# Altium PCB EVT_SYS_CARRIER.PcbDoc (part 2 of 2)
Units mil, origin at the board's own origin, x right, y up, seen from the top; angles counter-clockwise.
Board outline 3937.01 x 3149.61 mil, 4 copper layers (Top Layer, Mid-Layer 1, Mid-Layer 2, Bottom Layer), stack 63.036 mil thick; 92 components, 67 nets, 529 pads, 132 vias.
Unrouted connection lines stored in the file: 166.
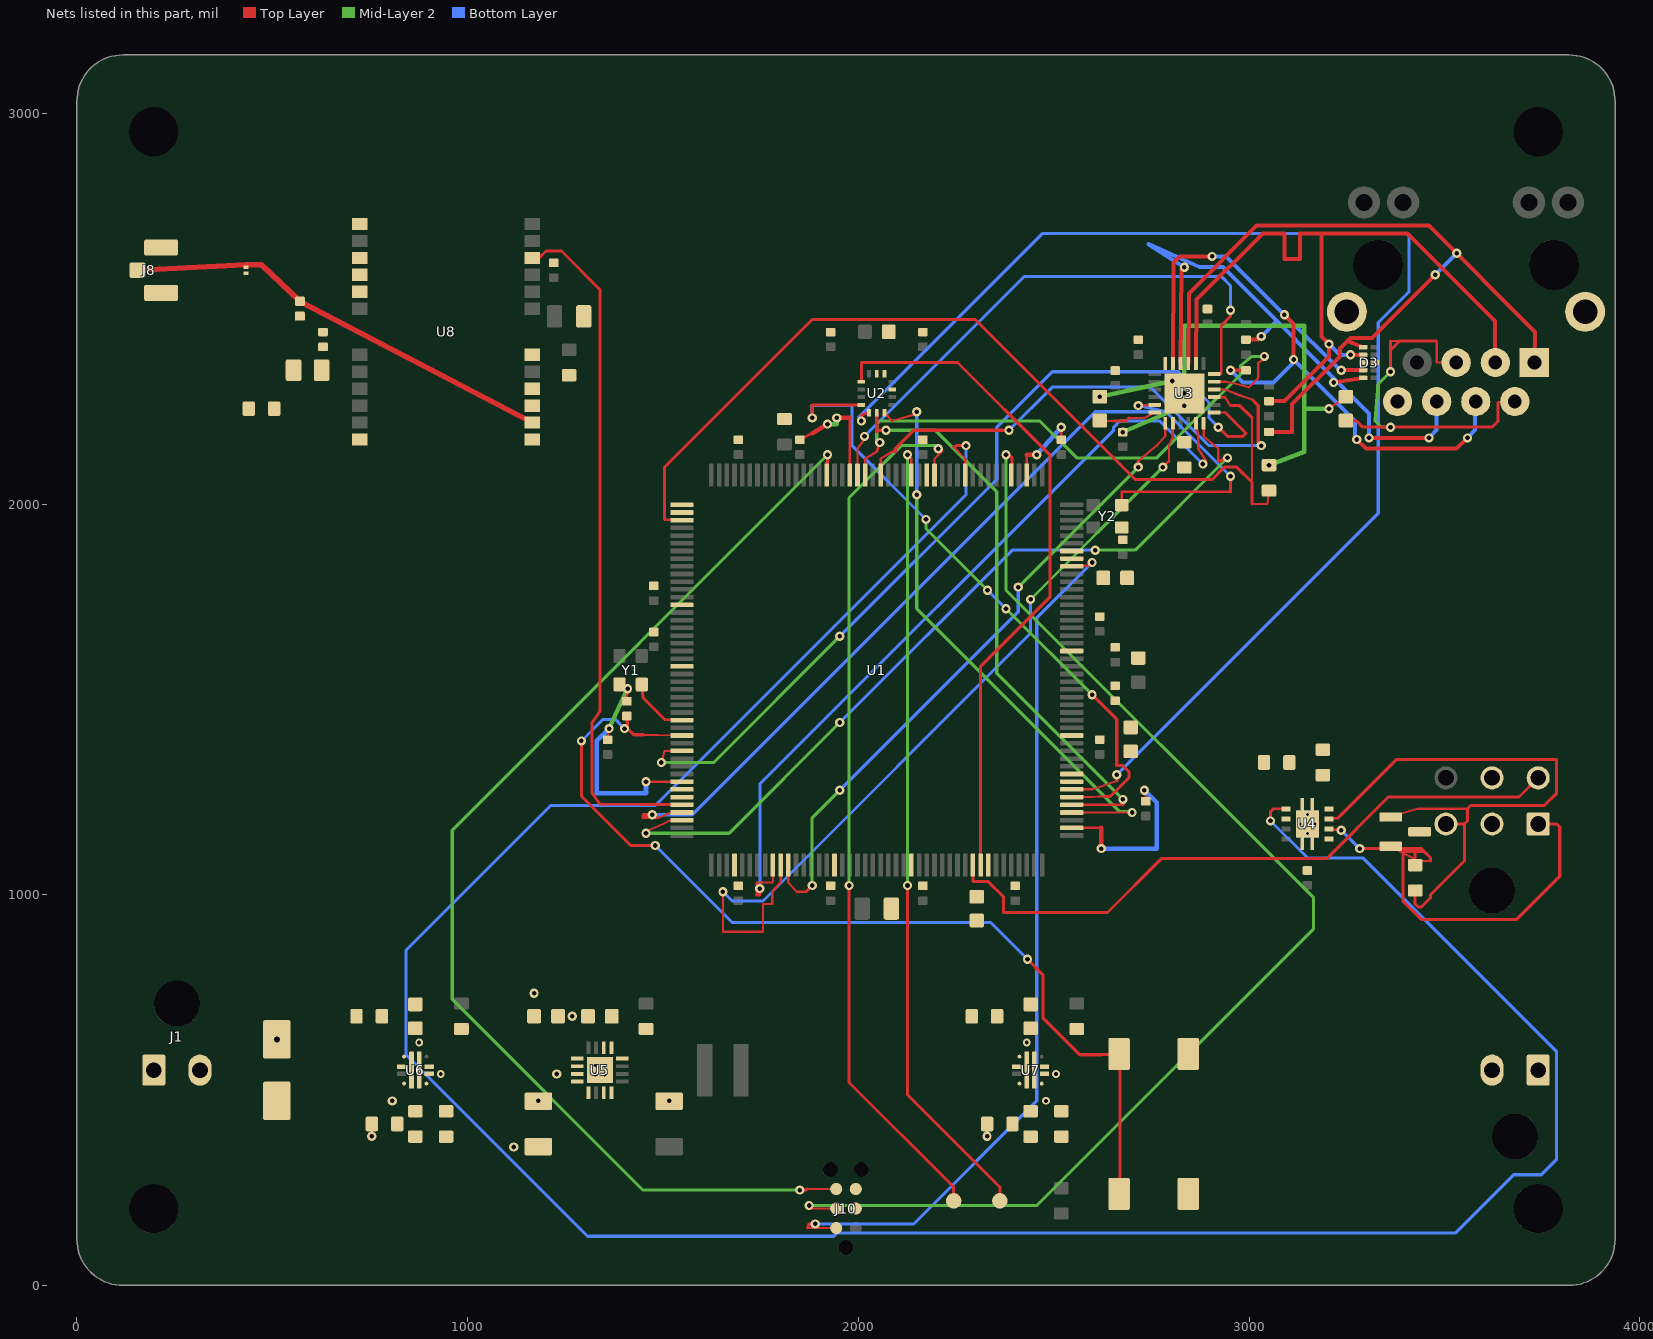
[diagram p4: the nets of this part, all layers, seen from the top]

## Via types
v1: diameter 23.62, hole 11.81, Top Layer to Bottom Layer, 121 vias
v2: diameter 19.68, hole 9.84, Top Layer to Bottom Layer, 5 vias
v3: diameter 15.75, hole 7.87, Top Layer to Bottom Layer, 4 vias
v4: diameter 31.5, hole 15.75, Top Layer to Bottom Layer, 2 vias

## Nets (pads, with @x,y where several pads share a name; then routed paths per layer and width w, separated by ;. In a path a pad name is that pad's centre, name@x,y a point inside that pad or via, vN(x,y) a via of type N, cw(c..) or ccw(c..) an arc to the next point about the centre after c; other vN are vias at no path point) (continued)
CAN_TX: U1.143 U4.1 | length 6963.6
  Top Layer w5.91: 2244.09,2145.67 2273.62,2116.14 U1.143@2273.62,2073.82
  Top Layer w7.87: 2244.09,2145.67 2251.97,2149.61 v1(2275.59,2149.61) ; v1(3055.12,1188.98) 3055.12,1212.6 3062.99,1220.47 U4.1@3094.49,1219.49
  Bottom Layer w7.87: v1(2275.59,2149.61) 2275.59,2023.62 1480.32,1228.35 1212.6,1228.35 842.52,858.27 842.52,590.55 1307.09,125.98 1937.01,125.98 1944.88,133.86 3527.56,133.86 3677.17,283.46 3748.03,283.46 3787.4,322.83 3787.4,598.43 3291.34,1094.49 3149.61,1094.49 v1(3055.12,1188.98)
DEBUG_RX: TP2.1 U1.150 | length 2063.5
  Top Layer w5.91: v1(2125.98,2125.98) 2135.83,2116.14 U1.150@2135.83,2073.82
  Top Layer w7.87: v1(2125.98,1023.62) 2125.98,488.19 2362.2,251.97 TP2.1@2362.2,216.54
  Mid-Layer 2 w7.87: v1(2125.98,1023.62) v1(2125.98,2125.98)
DEBUG_TX: TP1.1 U1.147 | length 2278.8
  Top Layer w5.91: U1.147@2194.88,2073.82 2194.88,2116.14 v1@2214.57,2135.83
  Top Layer w7.87: v1(1976.38,1023.62) 1976.38,519.68 2244.09,251.97 TP1.1@2244.09,216.54 ; v1(2204.72,2141.73) v1@2214.57,2135.83
  Mid-Layer 2 w7.87: v1(1976.38,1023.62) 1976.38,2015.75 2110.24,2149.61 2196.85,2149.61 v1(2204.72,2141.73)
ETH_50M: U1.41 U3.5 Y2.3 | length 2576.5
  Top Layer w5.91: 1448.82,1196.85 1488.19,1196.85 1519.68,1210.63 U1.41@1548.23,1210.63 ; Y2.3@2674.21,1997.05 2674.41,2031.5 2952.76,2031.5
  Top Layer w7.87: 1448.82,1196.85 1448.82,1204.72 v1(1472.44,1204.72) ; v1(2716.54,2251.97) 2724.41,2251.97 U3.5@2758.37,2253.94 ; 2952.76,2031.5 v1(2952.76,2070.87)
  Bottom Layer w7.87: v1(1472.44,1204.72) 1574.8,1204.72 2606.3,2236.22 2787.4,2236.22 ; v1(2716.54,2251.97) 2787.4,2236.22 ; v1(2952.76,2070.87) 2787.4,2236.22
ETH_CRS_DV: U1.53 U3.11 | length 2091.7
  Top Layer w5.91: 1740.16,1000 1740.16,1031.5 1781.5,1031.5 U1.53@1781.5,1075.79 ; U3.11@2864.17,2207.19 2870.08,2173.23 2870.08,2141.73 v1@2889.76,2110.24
  Top Layer w7.87: 1740.16,1000 1748.03,1000 v1(1748.03,1015.75) ; v1(2881.89,2102.36) v1@2889.76,2110.24
  Bottom Layer w7.87: v1(1748.03,1015.75) 1748.03,1283.46 2653.54,2188.98 2653.54,2196.85 2669.29,2212.6 2771.65,2212.6 v1(2881.89,2102.36)
ETH_CT: C63.1 pad.2@3680.32,2262.2 pad.5@3530.32,2362.2 | length 1348.1
  Top Layer w5.91: 3362.2,2417.32 3480.32,2417.32 3480.32,2362.2 pad.5@3530.32,2362.2
  Top Layer w7.87: C63.1@3248.03,2213.58 3275.59,2212.6 3291.34,2196.85 v1(3362.2,2196.85) 3622.05,2196.85 3637.8,2212.6 3637.8,2259.84 pad.2@3680.32,2262.2 ; 3362.2,2417.32 v1(3362.2,2338.58) 3362.2,2393.7 3385.83,2417.32 3480.32,2417.32
  Mid-Layer 2 w7.87: 3322.83,2212.6 3330.71,2307.09 ; 3322.83,2212.6 3338.58,2196.85 ; 3322.83,2212.6 3338.58,2196.85 ; 3322.83,2212.6 3330.71,2307.09 ; 3330.71,2307.09 v1(3362.2,2338.58) 3330.71,2307.09 ; 3338.58,2196.85 v1(3362.2,2196.85) 3338.58,2196.85
ETH_MDC: U1.33 U3.13 | length 2261.6
  Top Layer w5.91: v1(1496.06,1338.58) 1503.94,1368.11 U1.33@1548.23,1368.11 ; U3.13@2910.93,2234.25 2938.98,2234.25
  Top Layer w7.87: v1(2921.26,2196.85) 2944.88,2173.23 2984.25,2173.23 2992.13,2181.1 2938.98,2234.25
  Mid-Layer 2 w7.87: v1(1496.06,1338.58) 1629.92,1338.58 v1(1952.76,1661.42)
  Bottom Layer w7.87: v1(1952.76,1661.42) 2354.33,2062.99 2354.33,2196.85 2496.06,2338.58 2818.9,2338.58 2897.64,2259.84 2897.64,2220.47 v1(2921.26,2196.85)
ETH_MDIO: U1.42 U3.12 | length 2127.8
  Top Layer w5.91: v1(1456.69,1157.48) 1464.57,1165.35 1500,1181.1 1519.68,1190.94 U1.42@1548.23,1190.94 ; U3.12@2883.86,2207.19 2883.86,2173.23 2921.26,2141.73 2921.26,2110.24
  Top Layer w7.87: 2921.26,2110.24 2929.13,2110.24 2937.01,2118.11 v1(2944.88,2118.11)
  Mid-Layer 2 w7.87: v1(1456.69,1157.48) 1669.29,1157.48 v1(1952.76,1440.94) ; v1(2606.3,1881.89) 2708.66,1881.89 v1(2944.88,2118.11)
  Bottom Layer w7.87: v1(1952.76,1440.94) 2393.7,1881.89 v1(2606.3,1881.89)
ETH_NRST: R605.1 U1.3 U3.15 | length 2509.2
  Top Layer w5.91: U3.15@2910.93,2273.62 2938.98,2273.62 2952.76,2251.97 ; 3007.87,2220.47 3007.87,2000 3047.24,2000 R605.1@3051.18,2034.45
  Top Layer w7.87: U1.3@1548.23,1958.66 1503.94,1960.63 1503.94,2094.49 1881.89,2472.44 2299.21,2472.44 2708.66,2062.99 2905.51,2062.99 2937.01,2094.49 2968.5,2094.49 3007.87,2055.12 3007.87,2000 ; 2952.76,2251.97 2976.38,2251.97 3007.87,2220.47
ETH_RXD0: U1.54 U3.8 | length 2174.6
  Top Layer w5.91: v1(1653.54,1007.87) 1653.54,905.51 1755.91,905.51 1755.91,976.38 1779.53,976.38 1779.53,1007.87 1801.18,1031.5 U1.54@1801.18,1075.79 ; 2795.28,2110.24 2795.28,2149.61 2805.12,2173.23 U3.8@2805.12,2207.19
  Top Layer w7.87: v1(2779.53,2094.49) 2795.28,2110.24
  Mid-Layer 2 w7.87: v1(2440.94,1755.91) v1(2779.53,2094.49)
  Bottom Layer w7.87: v1(1653.54,1007.87) 1677.17,984.25 1755.91,984.25 2440.94,1669.29 v1(2440.94,1755.91)
ETH_RXD1: U1.55 U3.7 | length 1682.1
  Top Layer w5.91: U1.55@1820.87,1075.79 1820.87,1031.5 1842.52,1007.87 1866.14,1007.87 ; 2716.54,2110.24 2763.78,2149.61 2785.43,2173.23 U3.7@2785.43,2207.19
  Top Layer w7.87: 1866.14,1007.87 v1(1881.89,1023.62) ; v1(2716.54,2094.49) 2716.54,2110.24
  Mid-Layer 2 w7.87: v1(1881.89,1023.62) 1881.89,1196.85 v1(1952.76,1267.72) ; v1(2409.45,1787.4) v1(2716.54,2094.49)
  Bottom Layer w7.87: v1(1952.76,1267.72) 2409.45,1724.41 v1(2409.45,1787.4)
ETH_RXN: D3.5 pad.6@3480.32,2262.2 R604.1 U3.22 | length 1595.8
  Top Layer w10.24: U3.22@2824.8,2359.74 2826.77,2602.36 2830.71,2606.3 v1(2834.65,2606.3) ; R604.1@2992.13,2420.87 3023.62,2421.26 v1(3031.5,2429.13) ; v1(3216.54,2311.02) D3.5@3291.93,2322.83 ; v1(3307.09,2169.29) v1(3460.63,2169.29)
  Bottom Layer w10.24: v1(2834.65,2606.3) 2742.34,2665.35 2874.02,2606.3 2933.07,2606.3 3307.09,2232.28 v1(3307.09,2169.29) ; v1(3031.5,2429.13) 3070.87,2468.5 ; v1(3216.54,2311.02) 3216.54,2314.96 v1@3220.47,2318.9 ; v1(3460.63,2169.29) 3480.32,2188.98 pad.6@3480.32,2262.2
ETH_RXP: D3.4 pad.4@3580.32,2262.2 R603.1 U3.23 | length 1912.3
  Top Layer w10.24: U3.23@2805.12,2359.74 2807.09,2618.11 2822.83,2633.86 v1(2905.51,2633.86) ; v1(2952.76,2342.52) 2960.63,2342.52 R603.1@2992.13,2342.13 ; v1(3090.55,2484.25) 3114.17,2460.63 v1(3114.17,2370.08) ; v1(3236.22,2342.52) D3.4@3291.93,2342.52 ; v1(3275.59,2165.35) 3299.21,2141.73 3531.5,2141.73 v1(3559.06,2169.29)
  Bottom Layer w10.24: v1(2905.51,2633.86) 2940.94,2633.86 v1(3090.55,2484.25) 3232.28,2342.52 v1(3236.22,2342.52) ; v1(2952.76,2342.52) 2984.25,2311.02 3062.99,2311.02 v1@3118.11,2366.14 ; v1(3114.17,2370.08) 3271.65,2212.6 3271.65,2169.29 v1(3275.59,2165.35) ; v1(3559.06,2169.29) 3578.74,2188.98 pad.4@3580.32,2262.2
ETH_TX_EN: U1.154 U3.16 | length 1386.2
  Top Layer w5.91: U1.154@2057.09,2073.82 2057.09,2116.14 2086.61,2133.86 2094.49,2133.86 ; U3.16@2910.93,2293.31 2938.98,2293.31 2972.44,2279.53 3007.87,2267.72
  Top Layer w7.87: 2094.49,2133.86 2094.49,2141.73 2141.73,2188.98 v1(2385.83,2188.98) ; 3007.87,2267.72 3023.62,2251.97 3023.62,2157.48 v1(3031.5,2149.61)
  Bottom Layer w7.87: v1(2385.83,2188.98) 2496.06,2299.21 2748.03,2299.21 2897.64,2149.61 v1(3031.5,2149.61)
ETH_TXD0: U1.156 U3.17 | length 1495
  Top Layer w5.91: U1.156@2017.72,2073.82 2017.72,2116.14 2047.24,2133.86 v1(2055.12,2157.48) ; U3.17@2910.93,2312.99 2938.98,2312.99 2968.5,2307.09 3000,2299.21 3023.62,2322.83 3023.62,2362.2 v1@3039.37,2370.08
  Top Layer w7.87: v1@3039.37,2370.08 v1(3039.37,2377.95)
  Mid-Layer 2 w7.87: v1(2055.12,2157.48) 2047.24,2165.35 2047.24,2204.72 2055.12,2212.6 2464.57,2212.6 2559.06,2118.11 2763.78,2118.11 2978.35,2330.71 2978.35,2354.33 3007.87,2377.95 v1(3039.37,2377.95)
ETH_TXD1: U1.157 U3.18 | length 1476.1
  Top Layer w5.91: U1.157@1998.03,2073.82 1998.03,2116.14 1998.03,2141.73 2015.75,2165.35 v1(2015.75,2173.23) ; U3.18@2910.93,2332.68 2929.13,2332.68 2929.13,2456.69
  Top Layer w7.87: 2929.13,2456.69 2952.76,2480.32 v1(2952.76,2496.06)
  Bottom Layer w7.87: v1(2015.75,2173.23) 2425.2,2582.68 2929.13,2582.68 2952.76,2559.06 v1(2952.76,2496.06)
ETH_TXN: D3.2 pad.3@3630.32,2362.2 R602.1 U3.20 | length 1951.1
  Top Layer w10.24: U3.20@2864.17,2359.74 2866.14,2523.62 3035.43,2692.91 3090.55,2692.91 3090.55,2627.18 3129.92,2627.18 3129.92,2692.91 3405.51,2692.91 3629.92,2468.5 3629.92,2440.94 pad.3@3630.32,2362.2 ; R602.1@3051.18,2263.39 3090.55,2263.78 3204.72,2377.95 v1(3204.72,2409.45) 3185.04,2429.13 3185.04,2692.91 ; v1(3259.84,2381.89) D3.2@3291.93,2381.89
  Bottom Layer w10.24: v1(3204.72,2409.45) 3232.28,2381.89 v1(3259.84,2381.89)
ETH_TXP: D3.1 pad.1@3730.32,2362.2 R601.1 U3.21 | length 2094
  Top Layer w10.24: U3.21@2844.49,2359.74 2846.46,2539.37 3019.68,2712.6 3460.63,2712.6 3732.28,2440.94 pad.1@3730.32,2362.2 ; R601.1@3051.18,2184.65 3110.24,2185.04 3110.24,2255.91 3232.28,2377.95 3232.28,2397.64 3251.97,2417.32 ; D3.1@3291.93,2401.57 3251.97,2417.32 ; v1(3476.38,2586.61) 3314.96,2425.2 3259.84,2425.2 3255.91,2421.26 3251.97,2417.32
  Bottom Layer w10.24: v1(3476.38,2586.61) v1(3531.5,2641.73)
GND: C1.2 C2.2 C3.2 C4.2 C6D.2 C7D.2 C10.2 C11.2 C12.2 C13.2 C14.2 C15.2 C20.2 C21.2 C22.2 C40.2 C60.2 C61.2 C62.2 C63.2 C64.2 C65.2 C80.2 C81.2 C82.2 C100.2 C101.2 C102.2 C103.2 C104.2 C105.2 C106.2 C107.2 C108.2 C109.2 C110.2 C111.2 C112.2 C113.2 C114.2 C115.2 D1.2 D3.3 D3.8 D8.2 J1.2 J8.2 J10.3 J10.5 pad.2@2844.49,234.25 pad.2@2844.49,592.52 pad.2@3622.05,551.18 pad.2@3622.05,1181.1 pad.3@3436.52,1161.42 pad.5@3622.05,1299.21 R1.2 R2.2 R10.2 R41.2 R42.2 R63.2 R73.2 R81.2 R600.2 R605.2 U1.14 U1.22 U1.37 U1.48 U1.61 U1.71 U1.90 U1.102 U1.113 U1.126 U1.135 U1.148 U1.158 U2.6 U2.7 U2.9 U3.25 U4.2 U4.9 U5.5 U5.6 U5.15 U5.16 U5.17 U6.8 U7.8 U8.10 U8.12 U8.13 U8.24 Y1.2 Y2.2 | length 2972.3
  Top Layer w5.91: C115.2@1407.48,1495.28 v1(1409.45,1527.56) ; v1(1456.69,1289.37) U1.37@1548.23,1289.37 ; C113.2@1850.39,2164.57 1881.89,2181.1 ; U1.158@1978.35,2073.82 1978.35,2220.47 ; U1.135@2431.1,2073.82 2431.1,2125.98 ; C111.2@2519.69,2164.57 v1(2519.68,2196.85) ; U1.90@2546.26,1171.26 2622.05,1171.26 ; v1(2732.28,1267.72) C107.2@2736.22,1239.37 ; v1(3204.72,2244.09) C63.2@3248.03,2274.61 ; C102.2@1358.27,1396.85 v1(1362.2,1425.2) C102.2@1358.27,1396.85
  Top Layer w11.81: 1881.89,2181.1 v1(1921.26,2204.72) ; v1(1944.88,2220.47) 1978.35,2220.47 ; 2431.1,2125.98 v1(2456.69,2125.98) ; v1(2622.05,1118.11) 2622.05,1171.26
  Mid-Layer 2 w11.81: v1(1362.2,1425.2) v1(1409.45,1527.56) ; v1(1921.26,2204.72) 1944.88,2204.72 v1(1944.88,2220.47) ; v1(2618.11,2274.61) v1(2803.15,2314.96) ; v1(2677.16,2184.25) v1(2834.65,2251.97) ; v1(2834.65,2283.46) 2834.65,2456.69 3141.73,2456.69 3141.73,2133.86 v1(3051.18,2099.41) ; 3141.73,2244.09 v1(3204.72,2244.09)
  Bottom Layer w11.81: v1(1362.2,1425.2) 1330.71,1393.7 1330.71,1259.84 1456.69,1259.84 v1(1456.69,1289.37) ; v1(2456.69,2125.98) v1(2519.68,2196.85) ; v1(2622.05,1118.11) 2763.78,1118.11 2763.78,1236.22 v1(2732.28,1267.72)
  other v1: 1181.1,472.44 1515.75,472.44 1267.72,688.98
  other v2: 931.1,541.34 2505.91,541.34
  other v3: 1326.77,539.37 1350.39,539.37 1326.77,562.99 1350.39,562.99
  other v4: 511.81,629.92
GNSS_BCKP_LOCAL: R82.1 U8.22
GNSS_BIAS_FILTER: C82.1 L80.1 R80.2
GNSS_PPS: U1.40 U8.3 | length 1761.7
  Top Layer w7.87: U8.3@1165.35,2629.92 1171.26,2627.95 1181.1,2627.95 1200.79,2647.64 1240.16,2647.64 1338.58,2549.21 1338.58,1468.5 1318.9,1440.94 1318.9,1259.84 1338.58,1232.28 U1.40@1548.23,1230.31
GNSS_RF: D8.1 J8.1 L80.2 U8.11 | length 1123.8
  Top Layer w14.17: J8.1@155.51,2598.43 433.07,2612.6 472.44,2612.6 570.87,2518.9 U8.11@1165.35,2208.66
GNSS_RX_EXT: U1.96 U8.21
GNSS_TX_EXT: U1.97 U8.20
GNSS_VCC_RF: R80.1 U8.9
GNSS_VUSB_LOCAL: R81.1 U8.7
IMU_DRDY: U1.80 U2.4 | length 1752.9
  Top Layer w7.87: U2.4@2007.87,2312.99 2007.87,2362.2 2253.94,2362.2 2490.16,2125.98 2490.16,1761.81 2312.99,1584.65 U1.80@2312.99,1075.79
IMU_MISO: U1.94 U2.1 | length 1714.6
  Top Layer w5.91: U1.94@2546.26,1250 2598.43,1250 2629.92,1251.97
  Top Layer w7.87: v1(1881.89,2220.47) 1881.89,2253.94 U2.1@2007.38,2253.94 ; v1(2598.43,1511.81) 2661.42,1448.82 2661.42,1330.71 2677.17,1330.71 2692.91,1314.96 2692.91,1299.21 2645.67,1251.97 2629.92,1251.97
  Mid-Layer 2 w7.87: v1(2173.23,1960.63) 2173.23,1937.01 v1(2330.71,1779.53) ; v1(2377.95,1732.28) v1(2598.43,1511.81)
  Bottom Layer w7.87: v1(1881.89,2220.47) 1881.89,2251.97 1984.25,2251.97 1984.25,2181.1 1984.25,2149.61 v1(2173.23,1960.63) ; v1(2330.71,1779.53) v1(2377.95,1732.28)
IMU_MOSI: U1.95 U2.14 | length 3478
  Top Layer w5.91: U1.95@2546.26,1269.68 2598.43,1269.68 2661.42,1291.34
  Top Layer w7.87: v1(2007.87,2212.6) 2007.87,2228.35 U2.14@2027.56,2233.76 ; 2661.42,1291.34 v1(2661.42,1307.09)
  Bottom Layer w7.87: v1(2007.87,2212.6) 2000,2220.47 2472.44,2692.91 3401.57,2692.91 3409.45,2685.04 3409.45,2543.31 3330.71,2464.57 3330.71,1976.38 v1(2661.42,1307.09)
IMU_NSS: U1.92 U2.12 | length 1522.3
  Top Layer w5.91: U2.12@2066.93,2233.76 2086.61,2212.6 v1@2141.73,2228.35 ; U1.92@2546.26,1210.63 2598.43,1210.63 v1(2700.79,1210.63)
  Top Layer w7.87: v1@2141.73,2228.35 v1(2149.61,2236.22)
  Mid-Layer 2 w7.87: v1(2149.61,2023.62) 2149.61,1732.28 2669.29,1212.6 v1@2700.79,1212.6
  Bottom Layer w7.87: v1(2149.61,2023.62) v1(2149.61,2236.22)
IMU_SCK: U1.93 U2.13 | length 1487.8
  Top Layer w5.91: U1.93@2546.26,1230.31 2598.43,1230.32 2677.17,1230.32
  Top Layer w7.87: U2.13@2047.24,2233.76 2047.24,2185.04 2055.12,2188.98 v1(2070.87,2188.98) ; 2677.17,1230.32 v1(2677.17,1244.09)
  Mid-Layer 2 w7.87: v1(2070.87,2188.98) 2196.85,2188.98 2354.33,2031.5 2354.33,1566.93 v1(2677.17,1244.09)
MCU_HSE_25M: U1.29 Y1.3 | length 156.9
  Top Layer w7.87: Y1.3@1445.87,1538.39 1448.82,1503.94 1503.94,1448.82 U1.29@1548.23,1446.85
NetC60_1: C60.1 U3.6 | length 146.9
  Top Layer w5.91: C60.1@2618.11,2213.58 2653.54,2212.6 ; 2692.91,2220.47 2732.28,2220.47 U3.6@2758.37,2234.25
  Top Layer w7.87: 2653.54,2212.6 2685.04,2212.6 2692.91,2220.47
NetJ6_8: pad.8 pad.SH
NetR41_1: R41.1 U4.8
NetR42_1: R42.1 U4.5
NetR600_1: R600.1 U3.24
NRST: C115.1 pad.1@2667.32,234.25 pad.1@2667.32,592.52 U1.31 | length 2570.8
  Top Layer w5.91: 1448.82,1409.45 1527.56,1407.48 U1.31@1548.23,1407.48
  Top Layer w7.87: v1(1291.34,1393.7) 1291.34,1251.97 1417.32,1125.98 v1(1480.32,1125.98) ; v1(1401.57,1425.2) 1409.45,1433.07 C115.1@1407.48,1457.48 1409.45,1425.2 1425.2,1409.45 1448.82,1409.45 ; v1(2433.07,834.65) 2472.44,795.28 2472.44,685.04 2566.93,590.55 2622.05,590.55 pad.1@2667.32,592.52 2669.29,535.43 2669.29,291.34 pad.1@2667.32,234.25
  Bottom Layer w7.87: v1(1291.34,1393.7) 1346.46,1448.82 1377.95,1448.82 v1(1401.57,1425.2) ; v1(1480.32,1125.98) 1677.17,929.13 2338.58,929.13 v1(2433.07,834.65)
RADAR_12V: pad.1@3740.16,551.18 U7.6
  other v2: 2480.32,472.44
RADAR_CANH: pad.1@3362.7,1198.82 pad.3@3503.94,1181.1 R40.1 U4.7 | length 1577.3
  Top Layer w5.91: pad.1@3362.7,1198.82 3433.07,1220.47 3559.06,1220.47
  Top Layer w7.87: U4.7@3204.72,1193.9 3228.35,1196.85 3377.95,1346.46 3787.4,1346.46 3787.4,1259.84 3755.91,1228.35 3566.93,1228.35 3559.06,1220.47 3559.06,1188.98 3551.18,1181.1 ; R40.1@3425.2,1010.83 3425.2,976.38 3433.07,968.5 3440.94,968.5 3464.57,992.13 3464.57,1000 3551.18,1086.61 3551.18,1181.1 ; pad.3@3503.94,1181.1 3551.18,1181.1
RADAR_CANL: pad.1@3740.16,1181.1 pad.2@3362.7,1124.02 R40.2 U4.6 | length 1357.7
  Top Layer w5.91: pad.2@3362.7,1124.02 3433.07,1086.61 3464.57,1086.61
  Top Layer w7.87: U4.6@3204.72,1168.31 3228.35,1165.35 v1(3236.22,1165.35) ; v1(3283.46,1118.11) 3440.94,1118.11 ; R40.2@3425.2,1075.79 3425.2,1110.24 3433.07,1118.11 3440.94,1118.11 ; pad.1@3740.16,1181.1 3787.4,1181.1 3795.28,1173.23 3795.28,1047.24 3685.04,937.01 3440.94,937.01 3393.7,984.25 3393.7,1110.24 3448.82,1110.24 3464.57,1094.49 ; 3440.94,1118.11 3464.57,1094.49 ; 3440.94,1118.11 3464.57,1094.49 ; 3464.57,1094.49 3464.57,1086.61 3464.57,1094.49
  Bottom Layer w7.87: v1(3236.22,1165.35) v1(3283.46,1118.11)
RADAR_EFUSE_FLT: R7F.1 U1.2 U7.4
RADAR_REF: pad.4@3740.16,1299.21 U1.79 | length 1687.5
  Top Layer w7.87: U1.79@2293.31,1075.79 2293.31,1033.46 2332.68,1033.46 2372.05,994.09 2372.05,954.72 2637.8,954.72 2775.59,1092.52 3198.82,1092.52 3356.3,1250 3690.94,1250 pad.4@3740.16,1299.21
SWCLK: J10.4 U1.137 | length 3269.2
  Top Layer w5.91: v1@1870.08,196.85 J10.4@1943.5,196.85
  Top Layer w7.87: v1@1870.08,196.85 v1(1874.02,204.72) ; v1(2377.95,2125.98) 2385.83,2125.98 2393.7,2118.11 U1.137@2391.73,2073.82
  Mid-Layer 2 w7.87: v1(1874.02,204.72) 2456.69,204.72 3165.35,913.39 3165.35,992.13 2377.95,1779.53 v1(2377.95,2125.98)
SWDIO: J10.2 U1.124 | length 2290
  Top Layer w5.91: 1870.08,146.85 J10.2@1943.5,146.85
  Top Layer w7.87: 1870.08,146.85 1874.02,157.48 v1(1889.76,157.48) ; U1.124@2546.26,1840.55 2590.55,1842.52 v1(2598.43,1850.39)
  Bottom Layer w7.87: v1(1889.76,157.48) 2141.73,157.48 2456.69,472.44 2456.69,1708.66 v1(2598.43,1850.39)
SWO: J10.6 U1.161 | length 3029.8
  Top Layer w5.91: 1870.08,246.85 J10.6@1943.5,246.85
  Top Layer w7.87: v1(1850.39,244.09) 1866.14,244.09 1870.08,246.85 ; U1.161@1919.29,2073.82 1921.26,2118.11 v1(1921.26,2125.98)
  Mid-Layer 2 w7.87: v1(1850.39,244.09) 1448.82,244.09 960.63,732.28 960.63,1165.35 v1(1921.26,2125.98)
SYS_EFUSE_FLT: R6F.1 U1.1 U6.4
U5_PG: R5P.1 U5.4
U5_SS_LOCAL: C3.1 U5.9
U6_DVDT: C6D.1 U6.7
U6_ILIM_LOCAL: R1.1 U6.9
U6_OVLO_LOCAL: R62.2 R63.1 U6.2
U6_UVLO_LOCAL: R61.2 R62.1 U6.1
U7_DVDT: C7D.1 U7.7
U7_ILIM_LOCAL: R2.1 U7.9
U7_OVLO_LOCAL: R72.2 R73.1 U7.2
U7_UVLO_LOCAL: R71.2 R72.1 U7.1
VCAP1_LOCAL: C10.1 U1.81
VCAP2_LOCAL: C11.1 U1.125
VDDA_FILTERED: C13.1 C14.1 FB1.2 U1.38 U1.39
VIN_PROTECTED: C1.1 C4.1 R71.1 U5.10 U5.11 U5.12 U5.13 U6.6 U7.5
  other v1: 1118.11,354.33 2329.72,381.89 1228.35,541.34 1170.28,748.03
  other v2: 875.98,622.05 2431.1,622.05
VIN_RAW: D1.1 J1.1 R61.1 U6.5
  other v1: 754.92,381.89 807.09,472.44
pads on no net: D3.6 D3.7 D3.9 D3.10 J1.Un1 J10.Un1 J10.Un2 J10.Un3 U1.4 U1.5 U1.7 U1.8 U1.9 U1.10 U1.11 U1.12 U1.13 U1.16 U1.17 U1.18 U1.19 U1.20 U1.21 U1.24 U1.25 U1.26 U1.27 U1.28 U1.30 U1.32 U1.34 U1.35 U1.43 U1.44 U1.45 U1.46 U1.47 U1.50 U1.51 U1.52 U1.56 U1.57 U1.58 U1.59 U1.60 U1.63 U1.64 U1.65 U1.66 U1.67 U1.68 U1.69 U1.70 U1.73 U1.74 U1.75 U1.76 U1.77 U1.78 U1.83 U1.84 U1.85 U1.86 U1.87 U1.88 U1.89 U1.98 U1.99 U1.100 U1.101 U1.104 U1.105 U1.106 U1.107 U1.108 U1.109 U1.110 U1.111 U1.112 U1.115 U1.116 U1.117 U1.118 U1.119 U1.120 U1.121 U1.122 U1.123 U1.128 U1.129 U1.130 U1.131 U1.132 U1.133 U1.134 U1.138 U1.139 U1.140 U1.141 U1.144 U1.145 U1.146 U1.151 U1.152 U1.153 U1.155 U1.160 U1.162 U1.163 U1.164 U1.165 U1.167 U1.168 U1.169 U1.170 U1.173 U1.174 U1.175 U1.176 U2.2 U2.3 U2.10 U2.11 U3.2 U3.3 U3.4 U3.10 U3.14 U3.Un1 U3.Un2 U3.Un3 U3.Un4 U4.Un1 U4.Un2 U4.Un3 U4.Un4 U4.Un5 U5.7 U5.8 U5.Un1 U5.Un2 U5.Un3 U5.Un4 U6.3 U6.10 U6.Un1 U6.Un2 U6.Un3 U6.Un4 U7.3 U7.10 U7.Un1 U7.Un2 U7.Un3 U7.Un4 U8.1 U8.2 U8.4 U8.5 U8.6 U8.8 U8.14 U8.15 U8.16 U8.17 U8.18 U8.19 Y1.1 Y2.1

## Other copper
Top Layer:
  rectangle net GND: 2480.32,537.4 2505.91,545.28
  rectangle net GND: 1342.52,568.9 1371.06,598.43
  rectangle net GND: 1342.52,503.94 1371.06,533.46
  rectangle net GND: 1231.3,677.17 1267.72,700.79
  rectangle net GND: 905.51,537.4 931.1,545.28
  rectangle net RADAR_12V: 2450.79,474.41 2500,486.22
  rectangle net RADAR_12V: 2446.85,482.28 2454.72,511.81
  rectangle net 3V3: 2549.21,720.47 2568.9,748.03
  rectangle net 3V3: 1446.85,720.47 1466.54,748.03
  rectangle net 3V3: 974.41,720.47 994.09,748.03
  rectangle net 3V3: 1700.2,521.65 1799.21,580.71
  rectangle net 3V3: 1328.74,311.02 1515.75,320.87
  rectangle net 3V3: 1323.82,311.02 1333.66,509.84
  rectangle net 3V3: 1515.75,299.21 1700.2,358.27
  rectangle net 3V3: 1670.67,299.21 1729.72,551.18
  rectangle net BUCK_SW: 1391.73,516.93 1606.89,564.96
  rectangle net VIN_PROTECTED: 2425.2,590.55 2437.01,622.05
  rectangle net VIN_PROTECTED: 2320.87,381.89 2338.58,413.39
  rectangle net VIN_PROTECTED: 1275.59,484.25 1312.99,509.84
  rectangle net VIN_PROTECTED: 1228.35,509.84 1297.24,566.93
  rectangle net VIN_PROTECTED: 1118.11,342.52 1181.1,366.14
  rectangle net VIN_PROTECTED: 1158.46,688.98 1182.09,748.03
  rectangle net VIN_PROTECTED: 870.08,590.55 881.89,622.05
  rectangle net VIN_RAW: 852.36,482.28 860.24,511.81
  rectangle net VIN_RAW: 807.09,474.41 856.3,486.22
  rectangle net VIN_RAW: 746.06,381.89 763.78,413.39
  rectangle net VIN_RAW: 492.13,393.7 531.5,440.94
Mid-Layer 1:
  rectangle net GND: 2486.22,542.32 2513.78,629.92
  rectangle net GND: 1307.09,545.28 1370.08,629.92
  rectangle net GND: 1503.94,472.44 1527.56,629.92
  rectangle net GND: 1255.91,629.92 1279.53,688.98
  rectangle net GND: 1169.29,472.44 1192.91,629.92
  rectangle net GND: 911.42,542.32 938.98,629.92
  rectangle net GND: 3606.3,551.18 3637.8,602.36
  rectangle net GND: 299.21,551.18 330.71,602.36
  rectangle net GND: 3700.79,600.39 3858.27,651.57
  rectangle net GND: 2478.35,600.39 3700.79,659.45
  rectangle net GND: 2458.66,629.92 2498.03,728.35
  rectangle net GND: 2383.86,708.66 2478.35,748.03
  rectangle net GND: 2364.17,629.92 2403.54,728.35
  rectangle net GND: 923.23,600.39 2374.02,659.45
  rectangle net GND: 903.54,629.92 942.91,728.35
  rectangle net GND: 828.74,708.66 923.23,748.03
  rectangle net GND: 809.06,629.92 848.43,728.35
  rectangle net GND: 314.96,600.39 818.9,659.45
Mid-Layer 2:
  rectangle net 3V3: 2547.24,748.03 2570.87,952.76
  rectangle net 3V3: 1444.88,748.03 1468.5,952.76
  rectangle net 3V3: 972.44,748.03 996.06,952.76
  rectangle net 3V3: 1769.68,551.18 1828.74,952.76
  rectangle net 3V3: 984.25,923.23 3149.61,982.28
Bottom Layer:
  rectangle net RADAR_12V: 3751.97,338.58 3771.65,551.18
  rectangle net RADAR_12V: 2578.74,452.76 3771.65,500
  rectangle net RADAR_12V: 2562.99,330.71 2594.49,472.44
  rectangle net RADAR_12V: 2480.32,460.63 2578.74,484.25
  rectangle net VIN_PROTECTED: 2311.02,622.05 2334.65,850.39
  rectangle net VIN_PROTECTED: 2322.83,610.24 2431.1,633.86
  rectangle net VIN_PROTECTED: 2317.91,381.89 2341.54,850.39
  rectangle net VIN_PROTECTED: 1212.6,541.34 1244.09,850.39
  rectangle net VIN_PROTECTED: 1106.3,354.33 1129.92,850.39
  rectangle net VIN_PROTECTED: 1158.46,748.03 1182.09,850.39
  rectangle net VIN_PROTECTED: 875.98,834.65 984.25,866.14
  rectangle net VIN_PROTECTED: 860.24,622.05 891.73,850.39
  rectangle net VIN_PROTECTED: 984.25,791.34 2330.71,909.45
  rectangle net VIN_RAW: 791.34,330.71 822.83,472.44
  rectangle net VIN_RAW: 759.84,314.96 822.83,346.46
  rectangle net VIN_RAW: 181.1,330.71 212.6,551.18
  rectangle net VIN_RAW: 196.85,271.65 767.72,389.76

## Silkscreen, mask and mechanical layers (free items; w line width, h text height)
Top Overlay:
  region: 3357.87,1163.39 3338.98,1163.39 3348.43,1176.38
  lines w10: 2637.8,291.34 2633.86,291.34 2633.86,535.43 2637.8,535.43 ; 2696.85,291.34 2814.96,291.34 ; 2696.85,535.43 2814.96,535.43 ; 2874.02,291.34 2877.95,291.34 2877.95,535.43 2874.02,535.43 ; 3233.46,2554.72 3233.46,3040.94 3877.17,3040.94 3877.17,2554.72 ; 3233.66,2428.74 3233.46,2183.07 3877.17,2183.07 3877.17,2428.74 ; 3369.69,1101.97 3369.69,1100 3429.53,1100 3429.53,1139.37 ; 3369.69,1146.06 3369.69,1176.77 ; 3369.69,1220.87 3369.69,1222.83 3429.53,1222.83 3429.53,1183.46 ; 3596.39,594.09 3486.81,594.09 3486.81,235.04 3526.18,195.67 3836.02,195.67 3875.39,235.04 3875.39,594.09 3779.92,594.09 ; 3647.71,594.09 3700.39,594.09 ; 3884.45,2322.83 3884.45,2401.57 ; 3358.86,864.96 3358.86,1224.41 3885.24,1224.41 3885.24,864.96 3845.87,825.59 3398.23,825.59 3358.86,864.96
Mechanical 1:
  the board outline again, w3.94
Mechanical 4:
  lines w10: 2627.95,183.07 2627.95,643.7 2883.86,643.7 2883.86,183.07 2627.95,183.07 ; 3179.53,2167.32 3179.53,3056.69 3931.1,3056.69 3931.1,2167.32 3179.53,2167.32 ; 3323.62,1102.36 3364.17,1102.36 3364.17,1094.49 3435.04,1094.49 3435.04,1139.76 3475.59,1139.76 3475.59,1183.07 3435.04,1183.07 3435.04,1228.35 3364.17,1228.35 3364.17,1220.47 3323.62,1220.47 3323.62,1176.77 3364.17,1176.77 3364.17,1146.06 3323.62,1146.06 3323.62,1102.36 ; 3343.31,810.24 3343.31,1240.16 3454.72,1240.16 3454.72,1348.43 3789.37,1348.43 3789.37,1240.16 3900.79,1240.16 3900.79,810.24 3343.31,810.24 ; 3471.26,180.31 3471.26,609.84 3890.94,609.84 3890.94,180.31 3471.26,180.31
Mechanical 6:
  circle w10: c2755.91,413.39 r68.9
  region: 3425.2,1104.33 3374.02,1104.33 3374.02,1205.71 3386.81,1218.5 3425.2,1218.5
  lines w10: 3710.63,589.76 3740.16,551.18 3769.69,589.76 ; 3710.63,1220.08 3740.16,1181.1 3769.69,1220.08 ; 2637.8,295.28 2637.8,531.5 2874.02,531.5 2874.02,295.28 2637.8,295.28 ; 3237.8,2187.01 3237.8,3037.01 3872.83,3037.01 3872.83,2224.8 3826.18,2187.01 3237.8,2187.01 ; 3363.19,869.29 3363.19,1220.08 3880.91,1220.08 3880.91,869.29 3841.54,829.92 3402.56,829.92 3363.19,869.29 ; 3491.14,239.37 3491.14,589.76 3871.06,589.76 3871.06,239.37 3831.69,200 3530.51,200 3491.14,239.37
  text "'.Designator'" at 3714.64,2646.08 h39.37 r180
  text "'.Designator'" at 3423.51,1046.63 h28.35 r90
  text "'.Designator'" at 3781.37,890.56 h39.37 r180
  text "'.Designator'" at 3840.42,260.64 h39.37 r180
  text "'.Designator'" at 2788.99,254.06 h39.37 r90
